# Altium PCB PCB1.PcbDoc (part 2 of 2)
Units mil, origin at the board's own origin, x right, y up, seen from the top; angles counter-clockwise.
Board outline 3937.01 x 3937.01 mil, 4 copper layers (Top Layer, Int1 (PGND), Int2 (signal), Bottom Layer(AGND)), stack 43.712 mil thick; 137 components, 102 nets, 529 pads, 160 vias.
Unrouted connection lines stored in the file: 51.
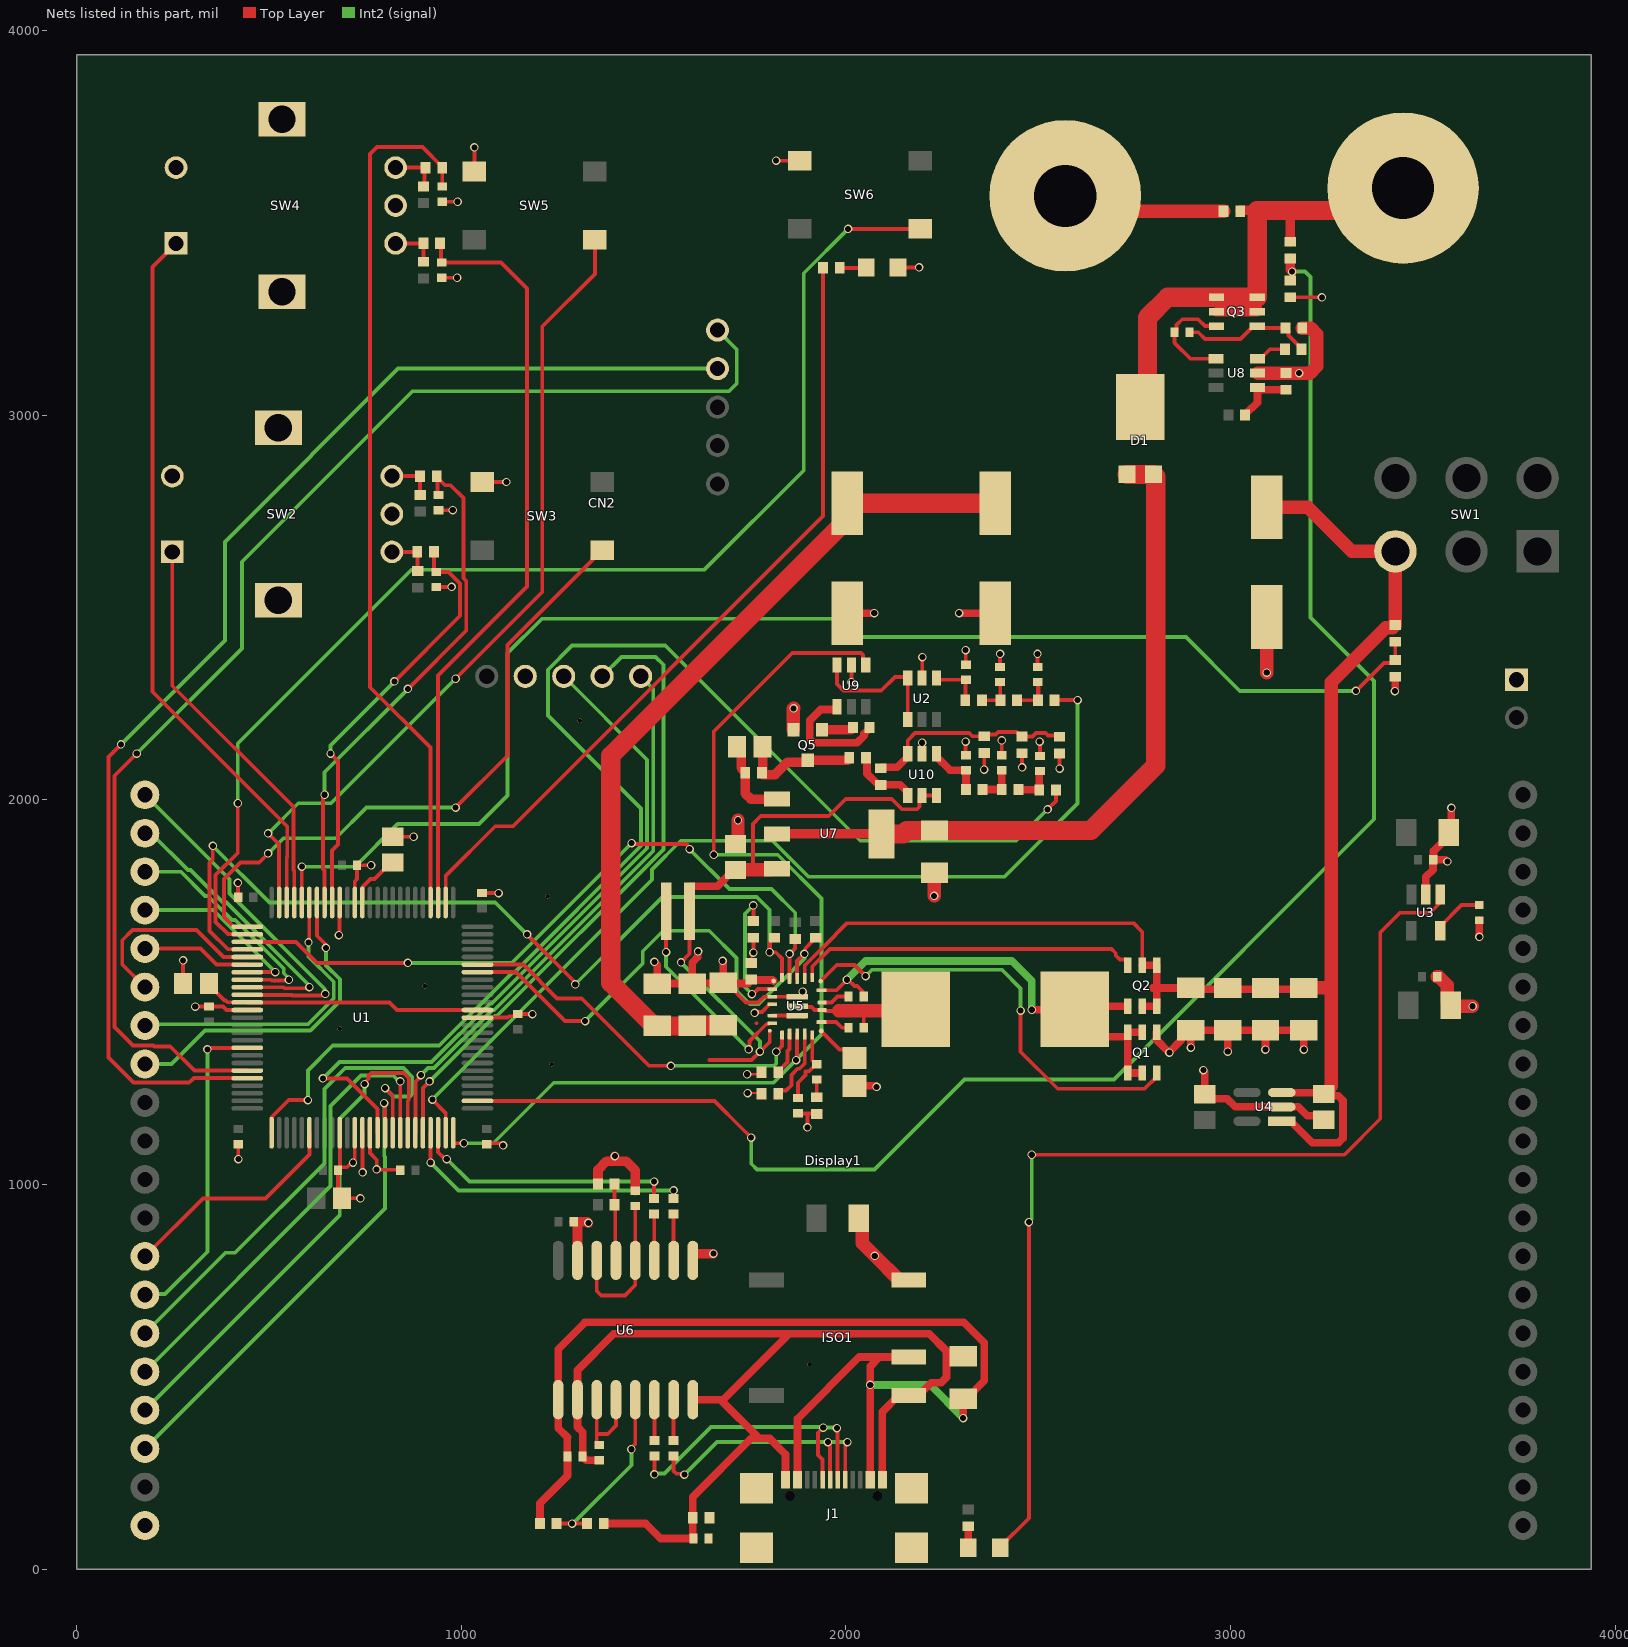
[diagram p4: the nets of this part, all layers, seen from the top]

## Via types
v1: diameter 22.05, hole 15.75, Top Layer to Bottom Layer(AGND), tented bottom, 154 vias
v2: diameter 11.81, hole 11.81, Top Layer to Bottom Layer(AGND), tented bottom, 6 vias

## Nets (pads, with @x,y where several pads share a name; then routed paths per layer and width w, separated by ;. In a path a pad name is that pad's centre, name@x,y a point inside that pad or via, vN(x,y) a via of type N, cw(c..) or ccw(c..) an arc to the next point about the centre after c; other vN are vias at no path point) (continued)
NetC11_2: C11.2 U1.63 | length 145
  Top Layer w10: U1.63@742.62,1732.91 742.97,1733.26 742.97,1772.92 763.99,1793.94 774.47,1793.94 817.43,1836.9 C11.2@821.37,1836.9
NetC12_2: C12.2 U1.39 U1.86 | length 729.3
  Top Layer w10: C12.2@343.46,1522.52 343.46,1518.59 383.68,1478.37 387.05,1478.37 392,1473.42 443.07,1473.42 U1.86@443.41,1473.07 813.34,1473.07 833.02,1453.39 U1.39@1041.84,1453.39
NetC17_1: C17.1 U5.22 | length 75.2
  Top Layer w10: U5.22@1937.96,1473.13 1962.39,1473.13 1977.62,1488.36 C17.1@2006.89,1488.36
NetC17_2: C17.2 L1.1 Q1.2 Q2.1 U5.23 | length 1333.4
  Top Layer w10: U5.23@1936.48,1504.62 1974.91,1504.62 v1(2002.28,1532) 2005.54,1532 2021.99,1515.55 2029.18,1515.55 2042.54,1502.19 2042.54,1492.08 C17.2@2046.26,1488.36
  Top Layer w20: v1(2483,1454) 2593.03,1454 L1.1@2594.68,1455.66 ; Q1.2@2732.6,1395.7 Q1.2@2732.6,1395.7 Q1.2@2770,1395.7 ; Q2.1@2732.68,1463.21 Q2.1@2732.75,1463.28 2602.31,1463.28 L1.1@2594.68,1455.66 ; Q1.2@2770,1289.4 Q1.2@2732.6,1289.4 2732.6,1383.67 2666.68,1383.67 L1.1@2594.68,1455.66
  Int2 (signal) w20: v1(2002.28,1532) 2002.28,1532.21 2051.07,1581 2431,1581 2483,1529 v1(2483,1454)
NetC18_1: C18.1 U5.20 | length 76.5
  Top Layer w10: U5.20@1936.48,1421.95 1974.41,1421.95 1989.17,1407.18 C18.1@2006.89,1407.18
NetC18_2: C18.2 L1.2 U5.21 U5.25 | length 359.1
  Top Layer w10: U5.25@1873,1463.28 1875.38,1460.9 1910.82,1460.9 1918.28,1453.44 1944.69,1453.44 1947.13,1451 1980.57,1451 ; C18.2@2046.26,1407.18 2046.26,1451
  Top Layer w35: 1980.57,1451 2046.26,1451 2176.64,1451 L1.2@2181.3,1455.66
NetC23_1: C23.1 U5.19 | length 115.8
  Top Layer w10: U5.19@1935.62,1398.69 1936.21,1398.1 1936.21,1397.13 1982.92,1350.43 2000.66,1350.43 C23.1@2022.03,1329.06
NetC24_1: C24.1 C25.1 C26.2 C27.2 C28.2 R6.2 U5.11 U5.12 U5.26 | length 2844.1
  Top Layer w10: v1(1532.19,1604.12) R6.2@1532.19,1710.31 ; C26.2@1681,1413.55 C26.2@1686.59,1419.15 ; v1(1747.02,1350.95) 1749.33,1353.25 1749.33,1372.72 1792.82,1416.21 1798.53,1416.21 U5.12@1801.23,1418.91 ; 1767.67,1419.15 1767.82,1418.99 ; U5.11@1808.53,1438.68 1854.03,1438.68 U5.26@1851.65,1436.3 ; U5.26@1873,1438.68 1887.35,1438.68 U5.26@1889.73,1436.3
  Top Layer w50: C26.2@1681,1413.55 1600,1413.55 C27.2@1600,1411.97 C28.2@1509.06,1411.97 1507.48,1413.55 1498.62,1413.55 1388.09,1524.08 1388.09,2114.47 2003,2729.38 C24.1@2003,2770.72 C25.1@2387.99,2770.72
  Int2 (signal) w10: v1(1532.19,1604.12) 1532.19,1565.78 v1(1747.02,1350.95)
NetC29_2: C29.2 C30.2 U5.18 | length 192.4
  Top Layer w10: C29.2@1875.38,1224.36 1875.38,1264.27 1895.07,1283.95 1895.07,1294.31 1903.82,1294.31 1921.8,1312.3 1912.37,1321.73 U5.18@1912.37,1388.48
NetC30_1: C30.1 R11.2 | length 46.3
  Top Layer w10: R11.2@1923.77,1226.59 C30.1@1923.77,1272.93
NetC31_1: C31.1 Q3.1 R15.1 R43.2 | length 345.3
  Top Layer w10: C31.1@2893.29,3215.63 2915.83,3215.63 2933.32,3198.13 3025.84,3198.13 3059.31,3231.6 Q3.1@3069.15,3231.6 3078.99,3231.6 3084.14,3226.45 R43.2@3142.91,3226.45 3150.7,3218.66 3150.7,3207.27 3184.65,3173.31 R15.1@3184.65,3171.35
NetC31_2: C31.2 Q3.3 U8.4 | length 290.6
  Top Layer w10: U8.4@2961.87,3146.72 2895.28,3146.72 2853.92,3188.08 C31.2@2853.92,3215.63 2859.55,3221.26 2859.55,3234.5 2874.37,3249.31 2915.54,3249.31 2933.26,3231.6 Q3.3@2962.85,3231.6
NetC32_2: C32.2 R16.1 U1.67 | length 1112.8
  Top Layer w10: v1(659.71,2120) 679.39,2100.31 679.39,1884 663.88,1868.49 U1.67@663.88,1732.91 ; v1(826.03,2307.74) 996.69,2478.4 996.69,2562.36 966.45,2592.61 C32.2@934.92,2592.61 934.32,2592.61 928.69,2598.24 R16.1@928.69,2644.57
  Int2 (signal) w10: v1(659.71,2120) 659.71,2141.42 v1(826.03,2307.74)
NetC33_1: C33.1 R17.1 U1.68 | length 1351
  Top Layer w10: U1.68@644.2,1732.91 644.2,1816.02 639.91,1820.31 639.91,2005.44 644.2,2009.73 v1(644.2,2012.99) ; v1(860.74,2288.19) 1012.69,2440.15 1012.69,2568.99 1005.13,2576.55 1005.13,2784.84 972.12,2817.84 957.52,2817.84 R17.1@938.2,2837.16 ; R17.1@935.9,2841.43 935.9,2839.46 R17.1@938.2,2837.16 ; C33.1@940.51,2792.21 938.2,2794.51 R17.1@938.2,2837.16
  Int2 (signal) w10: v1(644.2,2012.99) 644.2,2071.65 v1(860.74,2288.19)
NetC34_2: C34.2 R18.1 U1.53 | length 1995.6
  Top Layer w10: U1.53@939.48,1732.91 939.48,2323.48 1170.82,2554.82 1170.82,3329.01 1103.14,3396.69 C34.2@948.7,3396.69 946.73,3398.65 946.73,3444.65 R18.1@944.76,3446.62 R18.1@944.76,3448.59
NetC35_1: C35.1 R44.1 U1.54 | length 2278.7
  Top Layer w10: U1.54@919.79,1732.91 919.79,2135.59 762.75,2292.64 762.75,3678.89 780.86,3697 898.79,3697 950.35,3645.44 R44.1@950.35,3643.47 C35.1@950.35,3594.26
NetC39_2: C39.2 R22.2 R23.1 | length 96.1
  Top Layer w10: R23.1@2353.28,2258.74 R22.2@2401.68,2258.74 2401.1,2259.32 2401.1,2305.4 C39.2@2400.52,2305.98
NetC40_2: C40.2 R23.2 U2.1 | length 132.6
  Top Layer w10: U2.1@2235.35,2316.81 2240.27,2311.89 C40.2@2311.92,2311.89 2310.95,2310.92 2310.95,2259.71 R23.2@2309.98,2258.74
NetC41_2: C41.2 R21.2 R22.1 | length 135.4
  Top Layer w10: R22.1@2444.99,2258.74 R21.2@2499.12,2258.74 ; C41.2@2498.72,2305.98 2498.92,2305.78 2498.92,2258.94 R21.2@2499.12,2258.74 ; 2500.11,2292.23 2500.11,2259.72 R21.2@2499.12,2258.74
NetC46_1: C46.1 U6.3 U6.4 | length 247.6
  Top Layer w10: U6.3@1351.87,408.25 1351.87,351.44 ; C46.1@1358.37,322.04 1357.5,322.04 1351.87,327.67 1351.87,351.44 ; U6.4@1401.87,440.18 1401.87,372.68 1380.63,351.44 1351.87,351.44
  Top Layer w20: U6.3@1351.87,408.25 U6.3@1351.87,440.18
NetC47_1: C47.1 U6.12 U6.14 | length 396
  Top Layer w10: U6.14@1351.87,802.39 1351.87,722.91 1363.78,711 1425,711 ; 1429,715 1451.87,737.87 U6.12@1451.87,802.39 C47.1@1451.87,943.96
NetC49_2: C49.2 R6.1 U5.13 U7.3 U10.5 U10.6 | length 1636.5
  Top Layer w10: v1(1571,1577.29) 1593.21,1599.5 R6.1@1593.21,1710.31 ; 1645.28,1323.13 1754.42,1323.13 v1(1776.29,1345) 1801.89,1370.59 U5.13@1801.89,1399.55 ; 1758.15,1817.76 1758.15,1937.41 1778.26,1957.52 1955.23,1957.52 1999.45,2001.74 2118.92,2001.74 2145.38,1975.28 2184.72,1975.28 2191.13,1981.68 2191.13,2004.57 U10.5@2197.94,2011.38 U10.6@2235.35,2011.38
  Top Layer w20: R6.1@1593.21,1710.31 1593.21,1771.34 1596.99,1775.11 1665.92,1775.11 1708.56,1817.76 C49.2@1712.5,1817.76
  Top Layer w35: C49.2@1712.5,1817.76 1758.15,1817.76 1803.81,1817.76 1806.8,1820.75 U7.3@1820.58,1820.75
  Int2 (signal) w10: v1(1571,1577.29) 1776.29,1371.99 v1(1776.29,1345)
NetC50_2: C50.2 D1.2 U7.2 U7.4 | length 1886.7
  Top Layer w25: U7.2@1820.58,1911.3 U7.4@2092.23,1911.3
  Top Layer w50: U7.4@2092.23,1911.3 2149.08,1911.3 2157.9,1920.12 C50.2@2230,1920.12 2636.45,1920.12 2805.51,2089.18 2805.51,2839.8 D1.2@2799.45,2845.86 D1.2@2730.55,2845.86
NetC51_1: C51.1 Q5.3 R40.1 R41.1 | length 316.9
  Top Layer w25: R40.1@1781.25,2070.4 1781.25,2068.44 1784.16,2065.52 1815.27,2065.52 1847.56,2097.81 1897.22,2097.81 1900.47,2101.06 Q5.3@1900.47,2103.03 2004.32,2103.03 2008.2,2106.91 2008.2,2108.87 R41.1@2008.5,2109.17 ; R40.1@1781.25,2072.37 1783.22,2074.34 C51.1@1783.22,2137.68
NetC51_2: C51.2 R40.2 U7.1 | length 218.9
  Top Layer w25: C51.2@1716.29,2137.68 1727.41,2126.56 1727.41,2082.91 1737.94,2072.37 1737.94,2016.49 1752.59,2001.85 U7.1@1820.58,2001.85
NetC52_2: C52.2 R49.2 R50.1 | length 105.6
  Top Layer w20: R50.1@2448.25,2026.57 2448.86,2025.97 2501.96,2025.97 R49.2@2502.57,2025.36 2502.57,2073.94 2503.2,2074.57 C52.2@2504.54,2074.57
NetC53_2: C53.2 R47.1 R50.2 | length 99.7
  Top Layer w20: R47.1@2355.22,2026.57 R50.2@2404.95,2026.57 C53.2@2404.95,2076.54
NetC54_2: C54.2 R47.2 U10.1 | length 149
  Top Layer w20: U10.1@2235.35,2119.65 2235.35,2111.78 2270.58,2076.54 C54.2@2311.92,2076.54 R47.2@2311.92,2026.57
NetCN1_1: CN1.1 D1.1 Q3.2 R32.2 R39.2 | length 1449.9
  Top Layer w25: Q3.2@2962.85,3269 Q3.2@3069.15,3269 Q3.2@3069.15,3306.4 ; R39.2@3024.86,3530 3024.86,3531.97 3025.15,3532.26 3069.15,3532.26 ; R32.2@3154.72,3450.93 3154.72,3528.33 3158.65,3532.26 ; CN1.1@3304.7,3532.26 3390.38,3532.26 CN1.1@3448.45,3590.33
  Top Layer w50: D1.1@2765,3021.06 2784.03,3040.08 2784.03,3254.03 2836.4,3306.4 Q3.2@2962.85,3306.4 Q3.2@3069.15,3306.4 3069.15,3532.26 3158.65,3532.26 CN1.1@3304.7,3532.26
NetCN2_1: CN2.1 U1.20 | length 1468.7
  Top Layer w10: U1.20@880.42,1134.49 880.42,1266.79 894.55,1280.91 v1(894.55,1284.17)
  Int2 (signal) w10: v1(894.55,1284.17) 894.91,1284.17 913.13,1302.4 929.24,1302.4 1080.57,1453.72 1085.34,1453.72 1498.81,1867.19 1498.81,2288.19 CN2.1@1466,2321
NetCN2_2: CN2.2 U1.21 | length 1666.3
  Top Layer w10: U1.21@900.11,1134.49 900.11,1250.63 v1(917.42,1267.95)
  Int2 (signal) w10: v1(917.42,1267.95) 1087.2,1437.72 1091.97,1437.72 1525.06,1870.81 1525.06,2351.12 1505.17,2371 1416,2371 CN2.2@1366,2321
NetCN2_3: CN2.3 U1.15 | length 1863.9
  Top Layer w10: v1(640.02,1275.49) 702.25,1275.49 782,1195.75 U1.15@782,1134.49
  Int2 (signal) w10: v1(640.02,1275.49) 682.93,1318.4 922.62,1318.4 1073.94,1469.72 1078.71,1469.72 1482.81,1873.82 1482.81,2104.19 CN2.3@1266,2321
NetCN2_6: CN2.6 U1.95 | length 3376.9
  Top Layer w10: v1(156,2120) 98.34,2062.34 98.34,1409.31 146.15,1361.49 198.78,1361.49 201.37,1358.9 243.07,1358.9 306.06,1295.91 U1.95@443.41,1295.91
  Int2 (signal) w10: v1(156,2120) 429.53,2393.53 429.53,2618.94 872.59,3062 1696.06,3062 1716,3081.94 1716,3171 CN2.6@1666,3221
NetCN2_7: CN2.7 U1.96 | length 3326.8
  Top Layer w10: v1(115,2144) 82.34,2111.34 82.34,1329.47 147.31,1264.49 292.61,1264.49 304.33,1276.22 U1.96@443.41,1276.22
  Int2 (signal) w10: v1(115,2144) 385.31,2414.31 385.31,2670.67 835.64,3121 CN2.7@1666,3121
NetDisplay1_23: Display1.23 U1.16 | length 1235.7
  Top Layer w10: v1(799.34,1211.26) 801.33,1209.27 801.33,1134.83 U1.16@801.68,1134.49
  Int2 (signal) w10: Display1.23@177.17,312.99 801.68,937.51 801.68,1071.58 799.34,1073.92 v1(799.34,1211.26)
NetDisplay1_24: Display1.24 U1.19 | length 1366.8
  Top Layer w10: v1(748.18,1260.71) 748.18,1263.97 758.83,1274.62 758.83,1282.82 765.9,1289.89 850.17,1289.89 863.07,1276.99 863.07,1219.38 860.74,1217.04 U1.19@860.74,1134.49
  Int2 (signal) w10: Display1.24@177.17,412.99 683.57,919.4 683.57,1169.92 748.18,1234.53 v1(748.18,1260.71)
NetDisplay1_25: Display1.25 U1.18 | length 1244
  Top Layer w10: U1.18@841.05,1134.49 v1(841.05,1267.87)
  Int2 (signal) w10: Display1.25@177.17,512.99 659.96,995.79 659.96,1203.64 739.06,1282.73 822.92,1282.73 837.79,1267.87 v1(841.05,1267.87)
NetDisplay1_26: Display1.26 U1.17 | length 1354.5
  Top Layer w10: v1(801.68,1250.17) 821.37,1230.48 U1.17@821.37,1134.49
  Int2 (signal) w10: Display1.26@177.17,612.99 386.48,822.31 411.79,822.31 643.96,1054.48 643.96,1248.28 698.07,1302.4 849.37,1302.4 872.34,1279.42 872.34,1234.5 866.48,1228.64 823.2,1228.64 v1(801.68,1250.17)
NetDisplay1_27: Display1.27 U1.92 | length 840.3
  Top Layer w10: v1(339.53,1350.78) 342.79,1350.78 346.96,1354.96 U1.92@443.41,1354.96
  Int2 (signal) w10: Display1.27@177.17,712.99 179.11,714.94 229.67,714.94 339.53,824.8 v1(339.53,1350.78)
NetDisplay1_28: Display1.28 U1.6 | length 594.1
  Top Layer w10: Display1.28@177.17,812.99 327.81,963.64 490.83,963.64 604.83,1077.64 U1.6@604.83,1134.49
NetDisplay1_33: Display1.33 U1.69 | length 855.4
  Top Layer w10: U1.69@624.51,1732.91 624.51,1646.3 647.9,1622.91 v1(647.9,1615.04)
  Int2 (signal) w10: Display1.33@177.17,1312.99 246.36,1312.99 333.53,1400.16 607.24,1400.16 684.09,1477.01 684.09,1533.32 647.9,1569.51 v1(647.9,1615.04)
NetDisplay1_34: Display1.34 U1.70 | length 797.6
  Top Layer w10: v1(602.49,1629.07) 604.48,1631.06 604.48,1732.57 U1.70@604.83,1732.91
  Int2 (signal) w10: Display1.34@177.17,1412.99 180.33,1416.16 600.62,1416.16 668.09,1483.63 668.09,1526.69 602.49,1592.29 v1(602.49,1629.07)
NetDisplay1_35: Display1.35 U1.80 | length 511.6
  Top Layer w10: Display1.35@177.17,1512.99 118.11,1572.05 118.11,1634.59 145.02,1661.49 311.34,1661.49 381.65,1591.18 U1.80@443.41,1591.18
NetDisplay1_36: Display1.36 U1.81 | length 283.4
  Top Layer w10: Display1.36@177.17,1612.99 322.02,1612.99 363.51,1571.5 U1.81@443.41,1571.5
NetDisplay1_37: Display1.37 U1.82 | length 478.2
  Top Layer w10: U1.82@443.41,1551.81 v1(516.01,1551.81)
  Int2 (signal) w10: Display1.37@177.17,1712.99 354.83,1712.99 v1(516.01,1551.81)
NetDisplay1_38: Display1.38 U1.83 | length 609.9
  Top Layer w10: U1.83@443.41,1532.13 504.55,1532.13 506.89,1529.79 546.08,1529.79 548.42,1532.13 v1(551.68,1532.13)
  Int2 (signal) w10: Display1.38@177.17,1812.99 270.81,1812.99 333.83,1749.98 340.47,1749.98 403.48,1686.96 412,1686.96 538.03,1560.93 538.03,1549.03 551.68,1535.39 v1(551.68,1532.13)
NetDisplay1_39: Display1.39 U1.84 | length 759.1
  Top Layer w10: U1.84@443.41,1512.44 538.01,1512.44 540.35,1510.1 598.68,1510.1 601.57,1512.99 v1(604.83,1512.99)
  Int2 (signal) w10: Display1.39@177.17,1912.99 193.44,1912.99 289.13,1817.31 295.77,1817.31 379.02,1734.06 387.53,1734.06 602.52,1519.07 602.52,1515.3 v1(604.83,1512.99)
NetDisplay1_40: Display1.40 U1.85 | length 917.2
  Top Layer w10: U1.85@443.41,1492.76 559.2,1492.76 560.99,1490.97 641.94,1490.97 v1(646.07,1495.09)
  Int2 (signal) w10: Display1.40@177.17,2012.99 396.69,1793.47 396.69,1755.88 643.76,1508.81 643.76,1497.4 v1(646.07,1495.09)
NetJ1_A6: J1.A6 J1.B6 R28.1 | length 729.9
  Top Layer w10: R28.1@1551.87,294.16 1551.87,255.12 1559.41,247.58 1577.42,247.58 v1(1579.72,245.28) ; v1(1952.82,329.91) 1952.82,329.71 1958.48,324.05 1958.48,232.67 J1.A6@1958.66,232.48 ; J1.B6@1998.03,232.48 1998.07,232.52 1998.07,324.11 v1(2003.87,329.91)
  Int2 (signal) w10: v1(1579.72,245.28) 1664.36,329.91 1958.07,329.91 v1(2003.87,329.91)
NetJ1_A7: J1.A7 J1.B7 R30.1 | length 855.5
  Top Layer w10: v1(1501.87,246.06) R30.1@1501.87,294.16 ; J1.B7@1938.98,232.48 1938.98,284.64 1927.3,296.31 1927.3,354.38 1938.98,366.06 1939.51,366.06 v1(1940.88,367.42) ; v1(1976.46,366.06) 1978.35,364.17 J1.A7@1978.35,232.48
  Int2 (signal) w10: v1(1501.87,246.06) 1504.18,248.37 1527.71,248.37 1648.66,369.32 1938.98,369.32 v1(1940.88,367.42) ; v1@1940.61,367.69 1974.83,367.69 v1(1976.46,366.06)
NetLED1_2: LED1.2 R1.1 | length 69.1
  Top Layer w10: R1.1@1983.66,3382.88 2051.22,3382.88 LED1.2@2052.35,3384
NetLED2_1: LED2.1 U3.1 | length 2694.7
  Top Layer w10: LED2.1@2400.83,55.12 2400.83,57.09 2475.57,131.83 v1(2475.57,901.82) ; v1(2483,1077) 3295.65,1077 3389.17,1170.53 3389.17,1655.32 3440.2,1706.35 3519.19,1706.35 3544.95,1732.1 U3.1@3544.95,1753.59
  Int2 (signal) w10: v1(2475.57,901.82) 2483,909.25 v1(2483,1077)
NetLED2_2: LED2.2 R2.1 | length 56.2
  Top Layer w20: LED2.2@2318.16,55.12 R2.1@2318.15,111.3
NetQ1_3: Q1.3 U5.1 | length 1156.7
  Top Layer w10: U5.1@1934.21,1528.68 1976.1,1570.57 2022.03,1570.57 v1(2051.07,1541.53) ; v1(2454,1452) 2454,1345 2550.49,1248.51 2776.35,1248.51 2807.4,1279.56 Q1.3@2807.4,1289.4
  Int2 (signal) w10: v1(2051.07,1541.53) 2067.53,1558 2405.64,1558 2454,1509.64 v1(2454,1452)
NetQ2_3: Q2.3 U5.2 | length 894.1
  Top Layer w10: U5.2@1912.37,1538.09 1912.37,1566.23 1958.17,1612.04 2690.3,1612.04 2701.43,1600.91 2701.43,1595.4 2712.57,1584.27 2727.91,1584.27 2732.75,1579.43 Q2.3@2732.75,1569.58
NetQ5_1: Q5.1 R46.1 | length 84.1
  Top Layer w25: Q5.1@1937.87,2181.77 2014.06,2181.77 2017.94,2185.65 2017.94,2187.61 R46.1@2018.24,2187.91
NetR1_2: R1.2 U1.52 | length 2083.3
  Top Layer w10: U1.52@959.16,1732.91 959.16,1802.12 1088.02,1930.98 1133.98,1930.98 1940.36,2737.36 R1.2@1940.36,3382.88
NetR3_2: R3.2 U3.5 | length 136.5
  Top Layer w10: U3.5@3544.95,1659.1 3544.95,1670.91 3600.38,1726.35 R3.2@3646.65,1726.35
NetR4_1: R4.1 R5.2 U1.71 | length 3581.1
  Top Layer w10: U1.71@585.14,1732.91 v1(585.14,1825.97) ; v1(3325.96,2282.95) 3398.39,2355.38 3420.42,2355.38 R5.2@3428.15,2363.1 3428.15,2411.97 R4.1@3428.15,2410.99
  Int2 (signal) w10: v1(585.14,1825.97) 723.04,1825.97 834.35,1937.29 1046.22,1937.29 1119.74,2010.81 1119.74,2381.36 1209.22,2470.83 1975.94,2470.83 2023.65,2423.12 2883.64,2423.12 3023.81,2282.95 v1(3325.96,2282.95)
NetR7_1: R7.1 U1.78 U5.5 | length 1880.8
  Top Layer w10: U1.78@443.41,1630.55 569.86,1630.55 624.74,1575.67 v1(860.73,1575.67) ; v1(1442.34,1887.13) 1444.79,1884.69 1587.35,1884.69 1587.35,1880.64 1593.21,1874.78 v1(1593.21,1871.52) ; U5.5@1853.32,1535.63 v1(1853.32,1599.11) 1868.08,1613.88 R7.1@1868.08,1641.41
  Int2 (signal) w10: v1(860.73,1575.67) 1130.89,1575.67 v1(1442.34,1887.13) ; v1(1593.21,1871.52) 1696.67,1768.06 1806.27,1768.06 1868.08,1706.25 1868.08,1613.88 v1(1853.32,1599.11)
NetR8_1: R8.1 U1.79 U5.6 | length 2293.4
  Top Layer w10: v1(353.67,1880.2) 353.67,1844.18 345.14,1835.65 345.14,1659.22 393.14,1611.21 443.07,1611.21 U1.79@443.41,1610.87 ; v1(1170.97,1650.15) 1296,1525.12 v1(1296,1520.24) ; R8.1@1814.21,1641.41 1812.24,1641.41 1804.44,1633.62 1804.44,1631.65 1802.4,1629.6 1802.4,1604.67 v1(1801.31,1603.58) 1817.48,1603.58 1833.63,1587.43 U5.6@1833.63,1538.09
  Int2 (signal) w10: v1(353.67,1880.2) 500.96,1732.91 1088.2,1732.91 v1(1170.97,1650.15) ; v1(1296,1520.24) 1523.13,1747.37 1767.96,1747.37 1801.31,1714.02 v1(1801.31,1603.58)
NetR9_1: R9.1 U1.44 U5.4 | length 1336
  Top Layer w10: U1.44@1041.84,1551.81 1142.36,1551.81 1269.61,1424.56 v1(1321.63,1424.56) ; U5.4@1873,1535.63 1873,1580.41 1891.7,1599.11 v1(1891.7,1599.5) 1894.01,1601.8 1894.01,1613.61 1912.04,1631.65 1912.04,1633.62 1919.84,1641.41 R9.1@1921.81,1641.41
  Int2 (signal) w10: v1(1321.63,1424.56) 1471.56,1574.49 1471.56,1606.1 1524.86,1659.4 1644.51,1659.4 1715.45,1588.47 1715.45,1503.12 1750.36,1468.21 1772.15,1468.21 1891.7,1587.75 v1(1891.7,1599.5)
NetR10_2: R10.2 U5.15 | length 111.7
  Top Layer w10: R10.2@1823.79,1291.57 1823.79,1293.54 1848.02,1317.77 1848.02,1347.08 1853.39,1352.45 1853.39,1390.86 U5.15@1853.32,1390.94
NetR12_2: R12.2 U5.8 | length 346.6
  Top Layer w10: v1(1755.12,1494.69) 1758.38,1494.69 1771.26,1507.58 U5.8@1808.53,1507.58 ; v1(1758.84,1725.34) 1759.05,1725.13 1759.05,1684.93 R12.2@1759.26,1684.72
  Int2 (signal) w10: v1(1755.12,1494.69) 1755.12,1495.74 1737.24,1513.62 1737.24,1703.75 v1(1758.84,1725.34)
NetR13_1: R13.1 U5.17 | length 194.2
  Top Layer w10: R13.1@1823.79,1235.4 1823.79,1236.02 1831.58,1243.82 1844.15,1243.82 1858.24,1257.91 1858.24,1284.8 1874.02,1300.58 1878.71,1300.58 1892.68,1314.56 U5.17@1892.68,1390.94
NetR14_2: R14.2 R42.1 U8.1 | length 162.2
  Top Layer w20: R42.1@3037.65,3000.56 3037.65,3002.53 3054.59,3019.46 3056.56,3019.46 3070.13,3033.04 U8.1@3070.13,3071.92 3078.01,3071.92 3083.91,3066.01 R14.2@3143.89,3066.01
NetR15_2: R15.2 U8.3 | length 81.4
  Top Layer w10: U8.3@3070.13,3146.72 3078.01,3146.72 3102.63,3171.35 R15.2@3141.35,3171.35
NetR16_2: R16.2 R45.1 SW2.5 | length 116.5
  Top Layer w10: SW2.5@819.28,2644.57 R16.2@885.39,2644.57 885.86,2644.1 885.86,2595.04 R45.1@886.33,2594.57
NetR17_2: R17.2 R51.1 SW2.3 | length 122.1
  Top Layer w10: SW2.3@819.28,2841.43 R17.2@892.6,2841.43 R51.1@892.6,2792.65
NetR18_2: R18.2 R52.1 SW4.5 | length 120.3
  Top Layer w10: SW4.5@829.12,3446.62 R18.2@901.45,3446.62 R52.1@901.45,3398.65
NetR21_1: R21.1 U1.24 | length 2519.7
  Top Layer w10: v1(924.41,1220.42) 959.16,1185.67 U1.24@959.16,1134.49 ; R21.1@2542.43,2258.74 2542.72,2259.03 2602.02,2259.03 v1(2602.31,2259.32)
  Int2 (signal) w10: v1(924.41,1220.42) 1496,1792.02 1496,1819.13 1570.42,1893.54 1808.59,1893.54 1902.18,1799.95 2411.95,1799.95 2602.31,1990.31 v1(2602.31,2259.32)
NetR24_2: R24.2 R27.2 U6.5 | length 470.4
  Top Layer w10: R24.2@1247.74,118.19 v1(1288.09,118.19) R27.2@1326.87,118.19 ; v1(1442.13,311.41) 1442.13,314.67 1451.87,324.41 U6.5@1451.87,440.18
  Int2 (signal) w10: v1(1288.09,118.19) 1290.54,118.19 1442.13,269.78 v1(1442.13,311.41)
NetR25_1: R25.1 R26.1 U6.13 | length 200.2
  Top Layer w10: R26.1@1398.23,1001.04 R25.1@1398.23,947.1 1400.05,945.28 1400.05,804.21 U6.13@1401.87,802.39
NetR28_2: R28.2 U6.7 | length 106
  Top Layer w10: R28.2@1551.87,334.16 U6.7@1551.87,440.18
NetR29_1: R29.1 U6.10 | length 120.8
  Top Layer w10: U6.10@1551.87,802.39 R29.1@1551.87,923.16
NetR29_2: R29.2 U1.22 | length 739.7
  Top Layer w10: v1(919.79,1056.77) U1.22@919.79,1134.49
  Int2 (signal) w10: v1(919.79,1056.77) 992.06,984.5 v1(1551.87,984.5)
NetR30_2: R30.2 U6.6 | length 106
  Top Layer w10: R30.2@1501.87,334.16 U6.6@1501.87,440.18
NetR31_1: R31.1 U6.11 | length 121.2
  Top Layer w10: U6.11@1501.38,802.88 R31.1@1501.38,922.66
  Top Layer w20: R31.1@1500.88,923.16 R31.1@1501.38,922.66 ; U6.11@1501.38,802.88 U6.11@1501.87,802.39
NetR31_2: R31.2 U1.23 | length 687.9
  Top Layer w10: U1.23@939.48,1134.49 939.48,1083.63 954.88,1068.22 959.64,1068.22 v1(961.95,1065.92) ; R31.2@1500.88,963.16 v1(1500.88,1007.14)
  Int2 (signal) w10: v1(961.95,1065.92) 1020.73,1007.14 v1(1500.88,1007.14)
NetR32_1: R32.1 R33.2 U1.27 | length 4390.1
  Top Layer w10: U1.27@1041.84,1217.17 1657.9,1217.17 1727.81,1147.26 v1(1753.53,1121.53)
  Top Layer w25: R32.1@3154.72,3407.62 3154.72,3378.68 v1(3159.91,3373.48)
  Int2 (signal) w10: v1(1753.53,1121.53) 1753.53,1053.62 1768.18,1038.98 2073.74,1038.98 2307.7,1272.93 2696.59,1272.93 3373.03,1949.37 3373.03,2308.37 3207.87,2473.53 3207.87,3358.84 3193.22,3373.48 v1(3159.91,3373.48)
NetR36_2: R36.2 R37.2 R38.2 R48.1 U10.3 | length 558.6
  Top Layer w10: U10.3@2160.54,2119.65 2160.54,2111.78 2160.54,2154.34 2179.48,2173.28 2320.08,2173.28 2328.16,2165.2 R36.2@2359.37,2165.2 ; R36.2@2357.79,2166.78 2360.71,2169.71 2389.14,2169.71 2395.83,2176.39 2443.63,2176.39 R37.2@2455.81,2164.21 ; R37.2@2457.78,2164.21 R37.2@2455.81,2164.21 ; R38.2@2555.23,2164.05 2552.23,2167.05 2525.46,2167.05 2519.23,2173.28 2494.43,2173.28 2485.37,2164.21 R37.2@2455.81,2164.21
  Top Layer w20: R48.1@2090.68,2082.05 2093.47,2084.85 2133.61,2084.85 U10.3@2160.54,2111.78
NetR41_2: R41.2 R48.2 U10.4 | length 176.4
  Top Layer w20: R41.2@2051.8,2109.17 2054.6,2106.37 2054.6,2067.94 2081,2041.54 2087.88,2041.54 R48.2@2090.68,2038.75 2141.05,2038.75 2160.54,2019.26 U10.4@2160.54,2011.38
NetR44_2: R44.2 R53.1 SW4.3 | length 129.1
  Top Layer w10: SW4.3@829.12,3643.47 R44.2@907.04,3643.47 904.25,3640.68 904.25,3597.44 R53.1@901.45,3594.65
NetR46_2: R46.2 U9.4 | length 316.9
  Top Layer w20: U9.4@1976.5,2241.87 1976.5,2236.49 1974.69,2234.68 1934.69,2234.68 1906.12,2206.11 1906.12,2157.42 1915.49,2148.05 2028.56,2148.05 2047.03,2166.52 2047.03,2171.43 2058.75,2183.15 2058.75,2185.11 R46.2@2061.54,2187.91
NetR49_1: R49.1 U1.1 | length 3523.7
  Top Layer w10: U1.1@506.4,1134.49 506.75,1134.83 506.75,1174.49 551.28,1219.02 v1(601.12,1219.02) ; v1(2524.22,1975.28) 2545.88,1996.93 R49.1@2545.88,2025.36
  Int2 (signal) w10: v1(601.12,1219.02) 601.12,1296.27 665.72,1360.87 942.46,1360.87 1132.91,1551.32 1137.68,1551.32 1466.81,1880.45 1466.81,1977.26 1225,2219.07 1225,2337.98 1287.71,2400.69 1529.9,2400.69 2037.05,1893.54 2442.49,1893.54 v1(2524.22,1975.28)
NetSW2_1: SW2.1 U1.72 | length 1043
  Top Layer w10: SW2.1@248.41,2644.57 248.41,2296.59 563.12,1981.88 563.12,1816.85 565.46,1814.51 U1.72@565.46,1732.91
NetSW3_1: SW3.1 U1.76 | length 1679.8
  Top Layer w10: U1.76@443.41,1669.92 407.98,1669.92 382.39,1695.51 382.39,1793.8 425.77,1837.18 474.36,1837.18 v1(497.7,1860.52) ; v1(984.75,1979.54) 1119.74,2114.53 1119.74,2402.1 1341.17,2623.54 1341.17,2628.46 1361.77,2649.05 SW3.1@1366.69,2649.05
  Int2 (signal) w10: v1(497.7,1860.52) 537.07,1899.89 673.23,1899.89 752.88,1979.54 v1(984.75,1979.54)
NetSW4_1: SW4.1 U1.73 | length 1884.6
  Top Layer w10: SW4.1@258.25,3446.62 197.02,3385.4 197.02,2280.98 547.12,1930.88 547.12,1850.7 545.77,1849.36 U1.73@545.77,1732.91
NetSW5_1: SW5.1 U1.74 | length 2137
  Top Layer w10: v1(497.7,1912.77) 526.09,1884.38 U1.74@526.09,1732.91 ; v1(984.75,2314.73) 1210.19,2540.17 1210.19,3230.19 1347,3367 SW5.1@1347,3456.46
  Int2 (signal) w10: v1(497.7,1912.77) 575.89,1990.97 660.99,1990.97 v1(984.75,2314.73)
NetSW6_1: SW6.1 U1.77 | length 3211.6
  Top Layer w10: v1(418.71,1990.97) 418.71,1861.61 361.14,1804.03 361.14,1682.38 392.93,1650.58 443.07,1650.58 U1.77@443.41,1650.24 ; v1(2005.42,3484.42) SW6.1@2192.5,3484.42
  Int2 (signal) w10: v1(418.71,1990.97) 418.71,2145.84 871.11,2598.24 1632.1,2598.24 1890,2856.13 1890,3369 v1(2005.42,3484.42)
NetU1_25: U1.25 U5.16 U9.1 | length 2677.1
  Top Layer w10: U1.25@978.85,1134.49 978.85,1107.77 979.68,1106.93 v1(1006.4,1106.93) ; v1(1656.1,1857.01) 1656.1,2177.93 1860.11,2381.94 2038.68,2381.94 2044.54,2376.08 2044.54,2356.9 U9.1@2051.3,2350.13 ; v1(1870.05,1323.06) 1870.05,1326.32 1873,1329.28 U5.16@1873,1390.94
  Int2 (signal) w10: v1(1006.4,1106.93) 1082.77,1106.93 1240.11,1264.27 1811.25,1264.27 v1(1870.05,1323.06) 1936.57,1389.59 1936.57,1742.93 1822.5,1857.01 v1(1656.1,1857.01)
NetU1_45: U1.45 U5.14 | length 968.7
  Top Layer w10: U1.45@1041.84,1571.5 1161.11,1571.5 1248.97,1483.63 1312.82,1483.63 1488.09,1308.36 v1(1544.49,1308.36) ; v1(1818.67,1344.79) 1833.63,1359.74 U5.14@1833.63,1388.48
  Int2 (signal) w10: v1(1544.49,1308.36) 1812.82,1308.36 1818.67,1314.22 v1(1818.67,1344.79)
NetU2_3: U2.3 U2.4 U9.3 | length 363.5
  Top Layer w10: U9.3@1976.5,2350.13 1976.5,2300.58 1993.13,2283.96 2091.59,2283.96 2127.08,2319.45 2157.9,2319.45 U2.3@2160.54,2316.81 ; U2.4@2160.54,2208.54 U2.3@2160.54,2315.74
PGND: C13.1 C14.1 C15.1 C16.1 C19.1 C20.1 C21.1 C22.1 C24.2 C25.2 C26.1 C27.1 C28.1 C36.2 C37.1 C38.1 C44.1 C47.2 C48.2 C49.1 C50.1 CN3.1 ISO1.7 P1.1 Q1.1 Q5.2 R3.1 R14.1 R19.1 R26.2 R39.1 R43.1 U3.2 U4.2 U5.7 U5.9 U5.24 U6.9 U6.15 U8.2 U9.2 | length 4149
  Top Layer w10: C26.1@1681,1523.79 1689.86,1523.79 1691.44,1522.21 1719.2,1494.44 1719.2,1492.92 1739.46,1472.67 1771.21,1472.67 1786.44,1487.89 U5.9@1808.53,1487.89 U5.24@1873,1487.89 1884.97,1487.89 1887.35,1490.27 v1(1887.35,1500.96) ; v1(2013.9,2305.98) U9.2@2013.9,2350.13
  Top Layer w20: v1(1501.87,1578.69) 1501.87,1578.14 1509.06,1570.95 C28.1@1509.06,1522.21 C27.1@1600,1522.21 ; v1(1615.23,1605.96) 1614.84,1605.57 1614.84,1591.43 1600,1576.59 C27.1@1600,1522.21 ; v1(1679.24,1581) 1679.24,1580.45 1681,1578.69 C26.1@1681,1523.79 1680.21,1523 1600.79,1523 C27.1@1600,1522.21 ; C26.1@1691.44,1522.21 R19.1@1746.14,1522.21 ; 1772.02,1531.65 1808.82,1531.65 U5.7@1811.79,1528.68 ; C24.2@2003,2485.28 v1(2073.46,2485.28) ; v1(2294,2485.28) C25.2@2387.99,2485.28 ; Q1.1@2807.4,1395.7 2807.4,1376.01 v1(2840.87,1342.55) 2841.26,1342.94 2841.26,1345.29 2871.07,1375.11 2871.07,1383.97 2887.65,1400.54 C19.1@2896.51,1400.54 ; v1(2896.51,1355.8) C19.1@2896.51,1400.54 ; v1(2929,1297) 2929,1296.45 2933,1292.45 C38.1@2933,1234.46 2944.83,1222.63 2990.56,1222.63 3011.71,1201.48 U4.2@3133.01,1201.48 3176.12,1201.48 3199.12,1178.48 3231.8,1178.48 C37.1@3242.26,1168.01 ; v1(2992.57,1345) C22.1@2992.57,1400.43 ; v1(3090.51,1350.49) C21.1@3090.51,1400.42 ; v1(3190.4,1350.49) C20.1@3190.4,1400.42 3190.34,1400.48 C21.1@3090.51,1400.42 C22.1@2992.57,1400.43 2896.57,1400.48 C19.1@2896.51,1400.54 ; U3.2@3507.54,1753.59 3507.54,1799.42 3526.32,1818.2 3526.32,1843.31 C16.1@3526.95,1843.94 ; v1(3563.43,1839.51) 3562.88,1839.51 3558.44,1843.94 C16.1@3526.95,1843.94 ; v1(3574.21,1979) 3573.82,1978.61 3573.82,1921.67 C15.1@3567.16,1915 3567.16,1906.14 3527.58,1866.57 3527.58,1844.57 C16.1@3526.95,1843.94 ; v1(3646.65,1643.35) R3.1@3646.65,1686.35
  Top Layer w25: C48.2@1292.23,902.59 1292.33,902.49 1327.46,902.49 v1(1330.32,899.63) ; U6.15@1301.87,802.39 C48.2@1301.87,892.94 ; R26.2@1354.92,1001.04 1355.22,1001.34 1355.22,1037.85 1377.86,1060.49 1399.04,1060.49 ; v1(1399.04,1073.46) 1399.04,1060.49 ; C47.2@1451.87,983.33 1451.87,1037.13 1428.51,1060.49 1399.04,1060.49 ; U6.9@1601.87,802.39 1601.87,818.82 1603.06,820 v1(1655,820)
  Top Layer w35: C49.1@1712.5,1884.69 1713.08,1884.69 1719.2,1890.81 v1(1719.2,1946.69) ; Q5.2@1863.07,2181.77 1863.07,2236.9 v1(1864.02,2237.86) ; C44.1@2033.46,911.66 2042.54,902.59 2042.54,846.58 v1(2074.8,814.31) 2137.68,751.44 ISO1.7@2163.27,751.44 ; v1(2229,1750) 2230,1751 C50.1@2230,1809.88 ; CN3.1@2570.11,3570.33 2610.44,3530 R39.1@2981.55,3530 ; U8.2@3070.13,3109.32 R14.1@3143.89,3109.32 3206.31,3109.32 3224.26,3127.27 3224.26,3210.69 3208.5,3226.45 R43.1@3186.21,3226.45 ; v1(3094,2330.62) C36.2@3094,2475.28 ; C14.1@3537.07,1540.11 3540.96,1540.11 3563.43,1517.64 3563.43,1474.62 C13.1@3572.5,1465.55 ; C13.1@3578.27,1465.54 3580.61,1463.21 v1(3628.94,1463.21)
  other v1: 3178.34,3109.32
  other v2: 1905.51,531.75 1235.14,1311.91 684.07,1404.95 904.28,1515.82 1225,1749.12
SGND: C1.1 C2.1 C3.1 C4.1 C5.1 C6.1 C7.1 C8.1 C9.1 C10.1 C11.1 C12.1 C23.2 C29.1 C32.1 C33.2 C34.1 C35.2 C39.1 C40.1 C41.1 C52.1 C53.1 C54.1 CN2.4 Display1.21 LED1.1 R5.1 R10.1 R11.1 R12.1 R13.2 R19.2 R33.1 R36.1 R37.1 R38.1 SW2.2 SW2.4 SW2.6 SW2.7 SW3.4 SW4.2 SW4.4 SW4.6 SW4.7 SW5.4 SW6.4 U1.10 U1.12 U1.13 U1.14 U1.38 U1.64 U1.66 U1.87 U2.2 U5.10 U10.2 | length 2680
  Top Layer w6: v1(1743.15,1286.34) 1775.25,1286.34 R10.1@1780.48,1291.57 ; v1(1744.19,1237.37) 1778.51,1237.37 R13.2@1780.48,1235.4 ; v1@1754.18,1597.39 1754.18,1578.25 R19.2@1755.12,1577.31
  Top Layer w10: C12.1@276.54,1522.52 v1(276.54,1582.54) ; v1(308.03,1462.37) C4.1@343.83,1462.37 380.42,1462.37 389.41,1453.39 U1.87@443.41,1453.39 ; v1(418.71,1784.01) 419.2,1783.52 419.2,1747.29 C10.1@419.69,1746.8 ; v1(420,1065.92) C6.1@420,1104.32 ; C7.1@679.39,1037.13 679.39,973.81 C1.1@689.37,963.83 v1(737.6,963.83) ; v1(681.23,1647.93) 683.22,1649.92 683.22,1732.57 U1.66@683.57,1732.91 ; U1.10@683.57,1134.49 683.57,1043.27 685.02,1044.73 702.87,1044.73 716.9,1058.76 722.94,1058.76 U1.12@722.94,1134.49 ; U1.64@722.94,1732.91 722.94,1788.03 728.84,1793.94 C2.1@728.84,1829.81 v1(765.46,1829.81) ; U1.13@742.62,1134.49 742.97,1134.14 v1(742.97,1031.38) ; U1.14@762.31,1134.49 762.31,1081.34 780.09,1063.56 780.09,1039.21 v1(779.66,1038.77) ; v1@780.09,1038.77 780.91,1037.95 840.22,1037.95 C8.1@841.05,1037.13 ; C11.1@821.37,1903.83 v1(875.86,1903.83) ; C32.1@934.92,2553.24 v1(974.67,2553.24) ; C33.2@940.51,2752.84 v1(977.54,2752.84) ; C34.1@948.7,3357.31 v1(989.13,3357.31) ; C35.2@950.35,3554.89 v1(990.11,3554.89) ; SW5.4@1034.01,3633.63 v1(1034.01,3696.01) ; U1.38@1041.84,1433.7 1119.74,1433.7 1123.1,1437.05 1140.7,1437.05 C3.1@1146.33,1442.68 v1(1184.66,1442.68) ; C5.1@1053.69,1757.43 v1(1096.96,1757.43) ; SW3.4@1053.69,2826.21 v1(1117.04,2826.21) ; C9.1@1066.29,1104.31 1064.32,1104.31 1067.04,1107.03 1102.86,1107.03 v1(1108.44,1101.45) ; v1@1754.18,1597.39 v1(1759.26,1602.47) R12.1@1759.26,1641.41 ; v1(1762.34,1446.18) 1764.64,1448.49 1781.59,1448.49 1801.31,1468.21 U5.10@1808.53,1468.21 ; v1(1818.36,3661.58) SW6.4@1879.5,3661.58 ; C29.1@1875.38,1184.99 1876.24,1184.14 1900.15,1184.14 ; v1(1899.61,1148) 1900.15,1148.54 1900.15,1184.14 ; R11.1@1923.77,1183.28 1922.92,1184.14 1900.15,1184.14 ; LED1.1@2135.02,3384 v1(2190.01,3384) ; U10.2@2197.94,2119.65 v1(2197.94,2148.2) ; U2.2@2197.94,2316.81 2198.16,2317.02 2198.16,2370.73 v1(2198.37,2370.94) ; v1(2310.96,2151.25) 2310.96,2116.87 C54.1@2311.92,2115.91 ; v1(2310.93,2388.96) 2311.42,2388.47 2311.42,2351.75 C40.1@2311.92,2351.26 ; v1(2359.37,2078.51) R36.1@2359.37,2121.89 ; C39.1@2400.52,2345.35 v1(2400.52,2379.12) ; C53.1@2404.95,2115.91 v1(2404.95,2154.37) ; v1(2457.78,2084.42) R37.1@2457.78,2120.91 ; v1(2497.9,2379.12) 2497.9,2346.17 C41.1@2498.72,2345.35 ; v1(2503.55,2151.25) 2504.05,2150.76 2504.05,2114.44 C52.1@2504.54,2113.94 ; v1(2555.23,2081.16) R38.1@2555.23,2120.74 ; R33.1@3154.72,3306.43 v1(3237.39,3306.43)
  Top Layer w20: C23.2@2022.03,1256.17 2076.35,1256.17 2079.27,1253.24 v1(2079.83,1253.24) ; v1(3426.84,2282.4) 3426.84,2282.95 3428.15,2284.26 R5.1@3428.15,2319.8
  other v1: 718.21,1056.81
  other v2: 1308.18,2205.48
"USB Sheald": C42.2 J1.1 J1.2 J1.3 J1.4 R20.2
USB_GND: C42.1 C43.1 C45.1 C46.2 ISO1.1 J1.A1-B12 J1.B1-A12 R20.1 R27.1 U6.2 U6.8 | length 2996.1
  Top Layer w20: C46.2@1358.37,282.67 1325.08,282.67 1317.83,289.91 1315.87,289.91 1315.24,290.54 1315.24,355.95 1301.87,369.32 U6.2@1301.87,440.18 1301.87,517.1 1396.45,611.67 1852.02,611.67 ; R27.1@1370.18,118.19 1479.24,118.19 1518.26,79.17 C42.1@1603.35,79.17 1603.35,81.14 1601.38,83.1 R20.1@1601.38,132.95 1601.38,187.21 1753.93,339.76 1774.16,339.76 ; U6.8@1601.87,440.18 1673.73,440.18 ; J1.A1-B12@1842.52,232.48 1842.52,298.42 1801.18,339.76 1774.16,339.76 ; J1.B1-A12@2094.49,232.48 2094.49,408.25 2137.68,451.44 ISO1.1@2163.27,451.44 2188.86,451.44 2221.53,484.11 2247.11,484.11 2261.25,498.25 2261.25,553.37 ; C43.1@2304.56,553.37 2261.25,553.37 ; 1673.73,440.18 1680.53,440.18 1852.02,611.67 ; 1673.73,440.18 1774.16,339.76 ; 1852.02,611.67 2216.33,611.67 2261.25,566.75 2261.25,553.37
VBAT: C19.2 C20.2 C21.2 C22.2 C36.1 C37.2 Q2.2 R4.2 SW1.3 U4.1 U4.3 U5.3 | length 4033.4
  Top Layer w10: U5.3@1892.68,1535.63 1892.68,1569.33 1940.97,1617.62 1941.13,1617.62 2002.65,1679.14 2747.23,1679.14 2770.16,1656.22 Q2.2@2770.16,1569.58
  Top Layer w20: Q2.2@2770.16,1463.28 Q2.2@2807.56,1463.28 2807.56,1510.78 Q2.2@2807.56,1569.58 ; Q2.2@2770.16,1569.58 Q2.2@2797.79,1569.58 ; 2797.79,1510.78 2882.94,1510.78 2886.48,1507.24 2890.01,1510.78 C19.2@2896.51,1510.78 ; C19.2@2896.51,1507.24 C22.2@2992.57,1507.24 ; C22.2@2992.57,1510.66 C22.2@2992.57,1507.24 ; C21.2@3090.51,1510.66 C21.2@3090.51,1507.24 ; U4.1@3133.01,1164.08 3156.49,1164.08 3212.57,1108 3280.28,1108 3292,1119.72 3292,1218.03 3279.66,1230.36 3246.85,1230.36 C37.2@3242.26,1234.94 ; U4.3@3133.01,1238.88 3133.79,1238.1 C37.2@3242.26,1238.1 ; C20.2@3190.4,1510.66 3186.98,1507.24 C21.2@3090.51,1507.24 ; C22.2@2992.57,1507.24 C21.2@3090.51,1507.24
  Top Layer w35: C36.1@3094,2760.72 3200.27,2760.72 3315.06,2645.92 SW1.3@3428.15,2645.92 R4.2@3428.15,2454.29 3421.14,2447.28 3403.65,2447.28 3261.95,2305.58 3261.95,1510.66 ; C20.2@3190.4,1510.66 3261.95,1510.66 ; C37.2@3242.26,1234.94 3246.2,1234.94 3252.32,1241.07 3252.32,1245 3261.95,1254.63 3261.95,1510.66
VBUS: C43.2 C45.2 ISO1.3 J1.A4-B9 J1.B4-A9 R24.1 U6.1 | length 2988.3
  Top Layer w20: R24.1@1204.43,118.19 1204.43,170.72 1275.87,242.15 C45.2@1275.87,292.51 1275.64,292.73 1275.64,335.11 ; 1275.87,342.19 1251.87,366.18 U6.1@1251.87,440.18 1251.87,571.42 1321.63,641.17 2306.34,641.17 2359.49,588.02 2359.49,489.21 2313.42,443.14 C43.2@2304.56,443.14 v1(2304.56,392.53) ; J1.A4-B9@1874.02,232.48 1874.02,390.75 2034.71,551.44 2087.99,551.44 ; J1.B4-A9@2062.99,232.48 v1(2062.99,478.57) 2062.99,526.44 2087.99,551.44 ; ISO1.3@2163.27,551.44 2087.99,551.44
  Int2 (signal) w20: v1(2062.99,478.57) 2218.52,478.57 v1(2304.56,392.53)
pads on no net: CN2.5 CN2.8 CN2.9 CN2.10 Display1.1 Display1.2 Display1.3 Display1.4 Display1.5 Display1.6 Display1.7 Display1.8 Display1.9 Display1.10 Display1.11 Display1.12 Display1.13 Display1.14 Display1.15 Display1.16 Display1.17 Display1.18 Display1.19 Display1.20 Display1.29 Display1.30 Display1.31 Display1.32 ISO1.14 J1. J1.A5 J1.A8 J1.B5 J1.B8 SW1.1 SW1.4 SW1.5 SW1.6 SW3.2 SW3.3 SW5.2 SW5.3 SW6.2 SW6.3 U1.2 U1.3 U1.4 U1.5 U1.7 U1.8 U1.9 U1.11 U1.28 U1.29 U1.30 U1.31 U1.32 U1.33 U1.34 U1.35 U1.36 U1.40 U1.41 U1.42 U1.43 U1.46 U1.47 U1.48 U1.49 U1.51 U1.55 U1.56 U1.57 U1.58 U1.59 U1.60 U1.61 U1.62 U1.89 U1.90 U1.91 U1.93 U1.94 U1.97 U1.98 U1.99 U4.4

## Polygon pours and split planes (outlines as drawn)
PGND on Top Layer "top Layer(Pgnd)" (solid, remove dead copper, pour order 30): 0,0 3937.01,0 3937.01,3937.01 0,3937.01
NetC24_1 on Top Layer "booster_out" (solid, remove dead copper, pour order 28): 1900.47,1445.32 1900.47,1432.71 1899.06,1431.3 1896.02,1434.33 1796.8,1434.33 1796.8,1433.83 1743.53,1380.55 1349.05,1380.55 1350.96,1797.32 1548.47,1797.32 1543.5,1467.09 1681.19,1467.09 1702.81,1445.48 1792.31,1445.41
PGND on Top Layer "PGND" (solid, remove dead copper, pour order 25): 1451.87,1615.04 1463.78,1603.14 1463.78,1467.09 1781.91,1467.09 1792.29,1477.47 1792.52,1477.25 1909.01,1477.25 1909.01,1645.76 1826.07,1728.69 1504.45,1728.69 1451.87,1676.11
VBAT on Top Layer "VBAT" (solid, remove dead copper, pour order 27): 2750.47,1514.9 2750.47,1665.19 2853.62,1768.35 3246.2,1768.35 3334,1677.63 3334,1469 3317,1452 3315.57,1453.43 2760.31,1453.43 2760.31,1452.86 2751.27,1461.9 2751.27,1514.9
NetC17_2 on Top Layer "PGND" (solid, remove dead copper, pour order 26): 2578.85,1510.53 2739.46,1510.53 2751.27,1498.72 2750.47,1497.91 2750.47,1433.76 2771.47,1433.76 2787.72,1417.51 2787.72,1259.87 2672.36,1259.87 2578.85,1353.38
"USB Sheald" on Top Layer "USB_SHEALD" (solid, remove dead copper, pour order 0): 1633.51,301.63 1633.51,0 2298.43,0 2298.43,301.63
SGND on Bottom Layer(AGND) "SGND" (solid, remove dead copper, pour order 23): 0,0 3937.01,0 3937.01,3937.01 0,3937.01
SGND on Int2 (signal) "Signal Layer(AGND)" (solid, remove dead copper, pour order 29): 0,0 3937.01,0 3937.01,3937.01 0,3937.01
PGND on Int1 (PGND) "PGND" (solid, remove dead copper, pour order 24): 0,0 3937.01,0 3937.01,3937.01 0,3937.01

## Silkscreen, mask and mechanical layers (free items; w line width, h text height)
Top Overlay:
  text "SET CURRENT" at 1410,3353 h39.37 r180
  text "OUTPT ON/OFF" at 2149,2952 h39.37 r180
  text "SET VOLTAGE" at 1423.77,2563.87 h39.37 r180
  text "-" at 3853.35,2287.55 h39.37 r90
  text "+" at 3853.35,2192.62 h39.37 r90
  text "Power Supply / Simen Sollihogda / rev3 / .Print_Date" at 3019.6,150.49 h39.37
Bottom Overlay:
  text "-" at 3632.87,2287.55 h39.37 r90
  text "+" at 3635.26,2185.94 h39.37 r90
